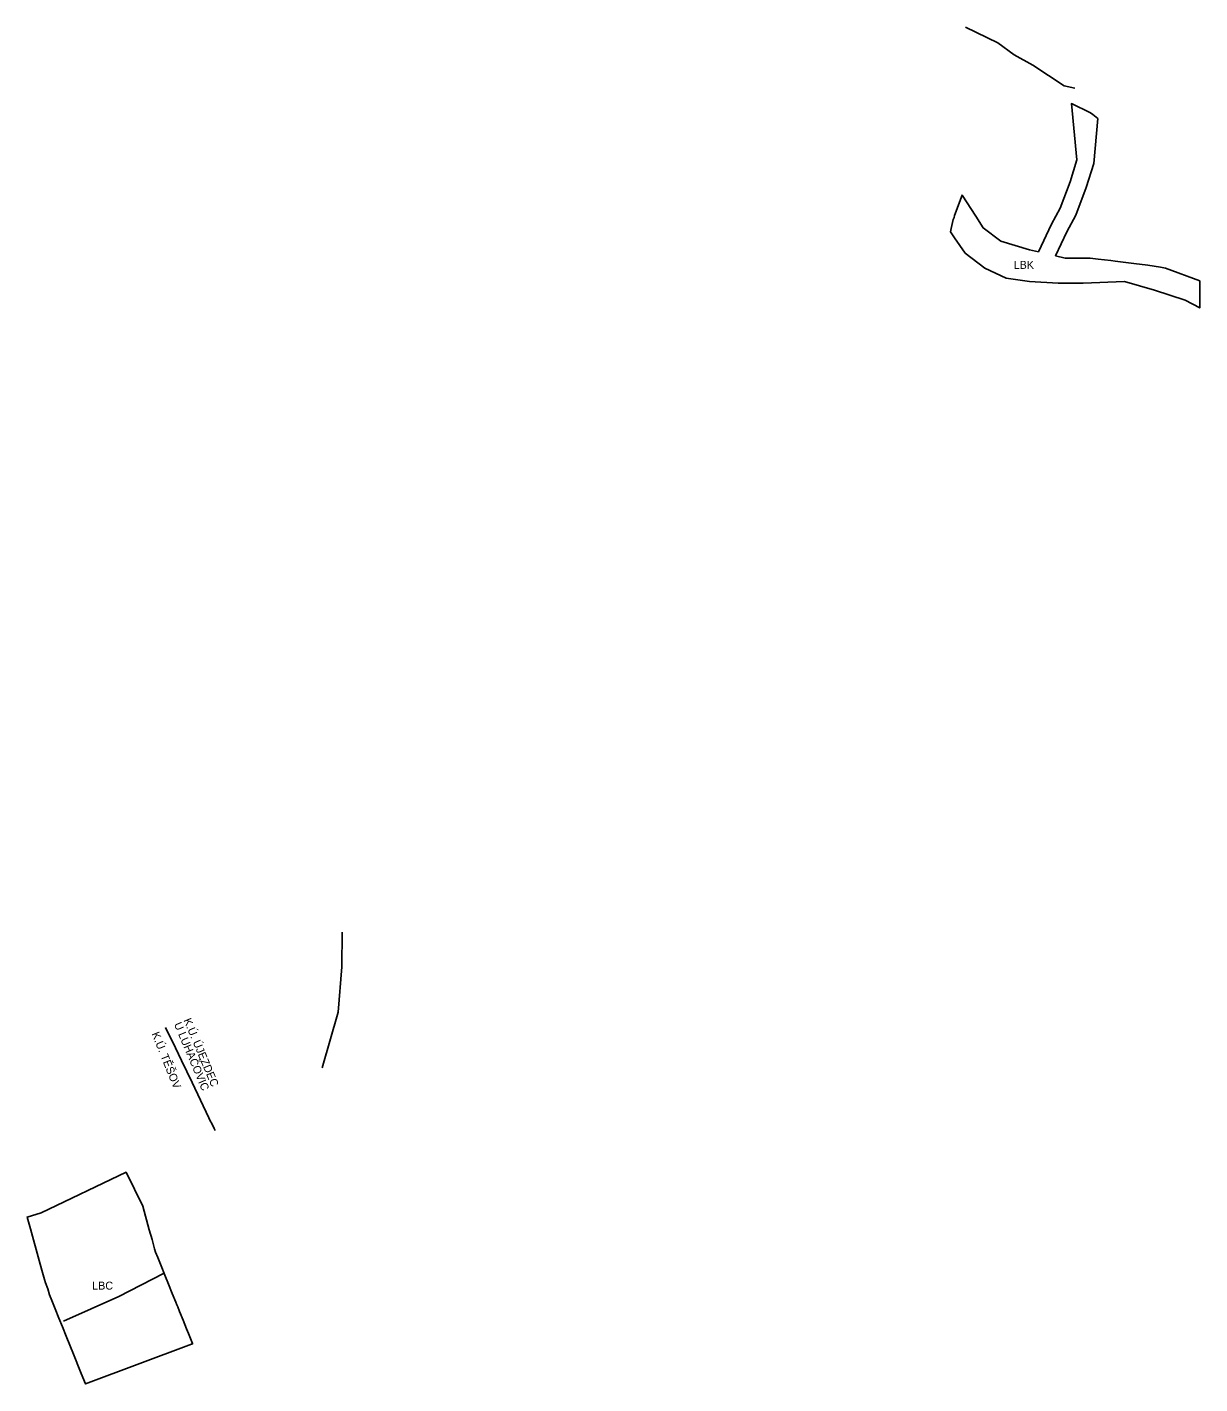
# Model space of a CAD drawing. Extents: x -521715 to -516578, y -1190280 to -1184826.
# Drawn here: x -521715 to -520689, y -1187586 to -1186399 of the extents above; entities that cross this region are included whole.
import ezdxf

# ---------------------------------------------------------------- set-up
doc = ezdxf.new("R2010")
doc.units = 0
for name, color, linetype in [('hr_ku_P_s', 7, 'Continuous'), ('kan_pater_j_n', 7, 'Continuous'), ('LBC_s', 7, 'Continuous'), ('LBK_s', 7, 'Continuous'), ('sil_II_n', 7, 'Continuous')]:
    doc.layers.add(name, color=color, linetype=linetype)

msp = doc.modelspace()

# ---------------------------------------------------------------- linework, layer by layer
at = {"layer": 'hr_ku_P_s'}
msp.add_lwpolyline([(-521550.3, -1187364.6), (-521551.1, -1187362.9), (-521553.3, -1187358.4), (-521554.5, -1187356), (-521555.7, -1187353.3), (-521570.5, -1187322.5), (-521579.7, -1187303.3), (-521585, -1187292.3), (-521593.6, -1187274.3)], dxfattribs=at)
at = {"layer": 'kan_pater_j_n'}
msp.add_lwpolyline([(-520798.4, -1186452.8), (-520807.7, -1186450.7), (-520835, -1186432.6), (-520851.5, -1186423.7), (-520865.7, -1186413.2), (-520894, -1186399.5)], dxfattribs=at)
at = {"layer": 'LBC_s'}
msp.add_line((-521569.9, -1187551.2), (-521569.9, -1187551.2), dxfattribs=at)
msp.add_lwpolyline([(-521704.2, -1187478.1), (-521711.8, -1187450.6), (-521711.9, -1187450.6), (-521711.9, -1187450.6), (-521714.7, -1187440.3), (-521702.4, -1187436.5), (-521628.2, -1187401), (-521613.6, -1187430.8), (-521613.6, -1187430.8), (-521607.9, -1187451.3), (-521605.5, -1187459.8), (-521603.2, -1187467.9), (-521602.4, -1187470.8), (-521600.5, -1187475.6), (-521597.5, -1187482.9), (-521594.2, -1187491.1), (-521591.1, -1187498.8), (-521587.8, -1187507), (-521584.6, -1187514.7), (-521583.7, -1187517.1), (-521583, -1187518.7), (-521581.4, -1187522.7), (-521578.3, -1187530.4), (-521575.2, -1187538), (-521573.5, -1187542.2), (-521571.8, -1187546.4), (-521570, -1187550.9), (-521569.9, -1187551.2), (-521570.9, -1187551.5), (-521663.6, -1187586.1), (-521664.5, -1187584), (-521664.5, -1187584), (-521667.9, -1187575.5), (-521667.9, -1187575.5), (-521667.9, -1187575.5), (-521674.1, -1187560.2), (-521674.1, -1187560.2), (-521677.3, -1187552.3), (-521677.3, -1187552.3), (-521677.3, -1187552.2), (-521680.5, -1187544.5), (-521680.5, -1187544.5), (-521683.8, -1187536.3), (-521683.8, -1187536.3), (-521683.8, -1187536.3), (-521686.9, -1187528.6), (-521686.9, -1187528.6), (-521690.2, -1187520.5), (-521690.2, -1187520.5), (-521690.2, -1187520.4), (-521693.2, -1187513.1), (-521693.2, -1187513.1), (-521695.1, -1187508.3), (-521696.7, -1187502.9), (-521698.8, -1187497.6), (-521699.5, -1187494.8), (-521699.5, -1187494.8), (-521701.8, -1187486.7), (-521701.8, -1187486.7), (-521704.2, -1187478.2), (-521704.2, -1187478.2)], close=True, dxfattribs=at)
at = {"layer": 'LBK_s'}
msp.add_lwpolyline([(-520838, -1186594.2), (-520830.1, -1186596), (-520818.6, -1186571.8), (-520811.1, -1186557.8), (-520802.5, -1186534.7), (-520796.5, -1186515.6), (-520801.3, -1186466.4), (-520784.6, -1186474.3), (-520782.5, -1186476), (-520778.1, -1186479.5), (-520781.8, -1186518.8), (-520788.3, -1186539.6), (-520797.4, -1186563.9), (-520805.2, -1186578.6), (-520815.2, -1186599.5), (-520806.7, -1186601.5), (-520784.8, -1186601.5), (-520777.9, -1186602.3), (-520766.8, -1186603.7), (-520763, -1186604.1), (-520746.6, -1186606.3), (-520734.4, -1186607.8), (-520723.4, -1186609.3), (-520719.1, -1186610.3), (-520689.1, -1186621.5), (-520689.1, -1186623.1), (-520689.1, -1186624.6), (-520689, -1186631.8), (-520689, -1186638.6), (-520689, -1186640.8), (-520689, -1186642.4), (-520689, -1186645), (-520701.9, -1186638.2), (-520728.5, -1186629.4), (-520755, -1186622), (-520791, -1186623.5), (-520812.9, -1186623.5), (-520838, -1186622), (-520858.3, -1186619.1), (-520877.1, -1186610.3), (-520894.3, -1186597.1), (-520903.7, -1186583.9), (-520907.2, -1186578.6), (-520906.4, -1186575.5), (-520904.6, -1186567.6), (-520903.9, -1186566), (-520903.5, -1186564.3), (-520897, -1186546.4), (-520884.9, -1186564.8), (-520878.6, -1186575.1), (-520863, -1186586.8)], close=True, dxfattribs=at)
at = {"layer": 'sil_II_n'}
for points in [[(-521456.6, -1187309.7), (-521442.7, -1187261), (-521439.4, -1187221.3), (-521439.1, -1187191.1)], [(-521595.4, -1187489.5), (-521634.5, -1187509.6), (-521683, -1187531.4)]]:
    msp.add_lwpolyline(points, dxfattribs=at)

# ---------------------------------------------------------------- texts
at = {"layer": 'hr_ku_P_s'}
for s, rotation, p in [('U LUHAČOVIC', 292.8133, (-521586.4, -1187271.5)), ('K.Ú. ÚJEZDEC ', 292.8133, (-521578.1, -1187268)), ('K.Ú. TĚŠOV', 291.9606, (-521606, -1187279.9))]:
    msp.add_text(s, height=7, rotation=rotation, dxfattribs=at).set_placement(p)
at = {"layer": 'LBK_s'}
for s, p in [('LBK', (-520851.8, -1186610.9)), ('LBC', (-521657.8, -1187503.7))]:
    msp.add_text(s, height=7, dxfattribs=at).set_placement(p)

doc.saveas('drawing.dxf')
